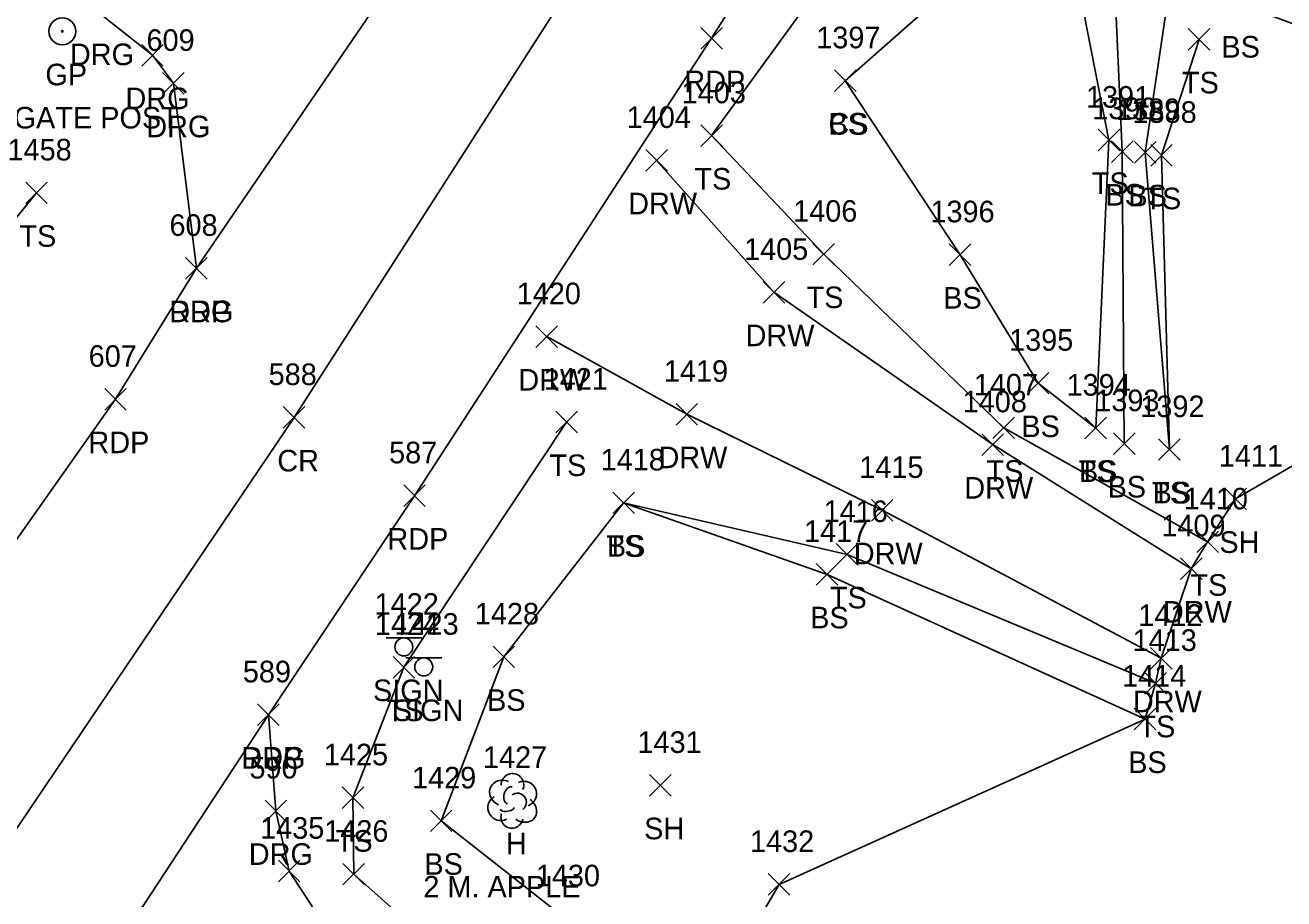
# Model space of a CAD drawing. Extents: x 1639430 to 1640195, y 612006 to 612917.
# Drawn here: x 1639665.7 to 1639782.3, y 612311.8 to 612392.7 of the extents above; entities that cross this region are included whole.
import ezdxf

# ---------------------------------------------------------------- set-up
doc = ezdxf.new("R2010")
doc.units = 0
for name, color, linetype in [('L_A', 7, 'Continuous'), ('L_C', 7, 'Continuous'), ('L_I', 7, 'Continuous'), ('L_TIC', 7, 'Continuous'), ('LELB', 7, 'Continuous'), ('LSOGP', 7, 'Continuous'), ('LTD', 7, 'Continuous'), ('P_A', 7, 'Continuous'), ('P_I', 7, 'Continuous'), ('P_TIC', 7, 'Continuous'), ('PET', 7, 'Continuous'), ('PRC', 7, 'Continuous'), ('R_A', 7, 'Continuous'), ('R_C', 7, 'Continuous'), ('R_I', 7, 'Continuous'), ('R_TIC', 7, 'Continuous'), ('RDG', 7, 'Continuous'), ('RDW', 7, 'Continuous'), ('RGP', 7, 'Continuous'), ('S_A', 7, 'Continuous'), ('S_I', 7, 'Continuous'), ('SSGN', 7, 'Continuous')]:
    doc.layers.add(name, color=color, linetype=linetype)

msp = doc.modelspace()

# ---------------------------------------------------------------- linework, layer by layer
at = {"layer": 'L_TIC'}
for points in [[(1639773.46, 612390.41), (1639775.46, 612392.41)], [(1639775.46, 612390.41), (1639773.46, 612392.41)], [(1639740.67, 612386.59), (1639742.67, 612388.59)], [(1639742.67, 612386.59), (1639740.67, 612388.59)], [(1639740.67, 612386.59), (1639742.67, 612388.59)], [(1639742.67, 612386.59), (1639740.67, 612388.59)], [(1639728.28, 612381.5), (1639730.28, 612383.5)], [(1639730.28, 612381.5), (1639728.28, 612383.5)], [(1639765.11, 612381.09), (1639767.11, 612383.09)], [(1639767.11, 612381.09), (1639765.11, 612383.09)], [(1639766.34, 612380.02), (1639768.34, 612382.02)], [(1639768.34, 612380.02), (1639766.34, 612382.02)], [(1639768.47, 612379.94), (1639770.47, 612381.94)], [(1639770.47, 612379.94), (1639768.47, 612381.94)], [(1639769.98, 612379.68), (1639771.98, 612381.68)], [(1639771.98, 612379.68), (1639769.98, 612381.68)], [(1639665.72, 612376.2), (1639667.72, 612378.2)], [(1639667.72, 612376.2), (1639665.72, 612378.2)], [(1639738.67, 612370.52), (1639740.67, 612372.52)], [(1639740.67, 612370.52), (1639738.67, 612372.52)], [(1639751.31, 612370.47), (1639753.31, 612372.47)], [(1639753.31, 612370.47), (1639751.31, 612372.47)], [(1639758.54, 612358.57), (1639760.54, 612360.57)], [(1639760.54, 612358.57), (1639758.54, 612360.57)], [(1639714.84, 612354.96), (1639716.84, 612356.96)], [(1639716.84, 612354.96), (1639714.84, 612356.96)], [(1639755.35, 612354.43), (1639757.35, 612356.43)], [(1639757.35, 612354.43), (1639755.35, 612356.43)], [(1639763.88, 612354.41), (1639765.88, 612356.41)], [(1639765.88, 612354.41), (1639763.88, 612356.41)], [(1639763.88, 612354.41), (1639765.88, 612356.41)], [(1639765.88, 612354.41), (1639763.88, 612356.41)], [(1639766.53, 612352.97), (1639768.53, 612354.97)], [(1639768.53, 612352.97), (1639766.53, 612354.97)], [(1639770.71, 612352.42), (1639772.71, 612354.42)], [(1639772.71, 612352.42), (1639770.71, 612354.42)], [(1639770.71, 612352.42), (1639772.71, 612354.42)], [(1639772.71, 612352.42), (1639770.71, 612354.42)], [(1639776.85, 612347.84), (1639778.85, 612349.84)], [(1639778.85, 612347.84), (1639776.85, 612349.84)], [(1639720.13, 612347.48), (1639722.13, 612349.48)], [(1639722.13, 612347.48), (1639720.13, 612349.48)], [(1639720.13, 612347.48), (1639722.13, 612349.48)], [(1639722.13, 612347.48), (1639720.13, 612349.48)], [(1639774.25, 612343.87), (1639776.25, 612345.87)], [(1639776.25, 612343.87), (1639774.25, 612345.87)], [(1639740.84, 612342.7), (1639742.84, 612344.7)], [(1639742.84, 612342.7), (1639740.84, 612344.7)], [(1639738.98, 612340.85), (1639740.98, 612342.85)], [(1639740.98, 612340.85), (1639738.98, 612342.85)], [(1639709.03, 612333.21), (1639711.03, 612335.21)], [(1639711.03, 612333.21), (1639709.03, 612335.21)], [(1639699.76, 612332.25), (1639701.76, 612334.25)], [(1639701.76, 612332.25), (1639699.76, 612334.25)], [(1639769.43, 612330.76), (1639771.43, 612332.76)], [(1639771.43, 612330.76), (1639769.43, 612332.76)], [(1639768.45, 612327.45), (1639770.45, 612329.45)], [(1639770.45, 612327.45), (1639768.45, 612329.45)], [(1639723.54, 612321.31), (1639725.54, 612323.31)], [(1639725.54, 612321.31), (1639723.54, 612323.31)], [(1639695.04, 612320.16), (1639697.04, 612322.16)], [(1639697.04, 612320.16), (1639695.04, 612322.16)], [(1639703.22, 612318.02), (1639705.22, 612320.02)], [(1639705.22, 612318.02), (1639703.22, 612320.02)], [(1639695.12, 612313.08), (1639697.12, 612315.08)], [(1639697.12, 612313.08), (1639695.12, 612315.08)], [(1639734.53, 612312.13), (1639736.53, 612314.13)], [(1639736.53, 612312.13), (1639734.53, 612314.13)]]:
    msp.add_lwpolyline(points, dxfattribs=at)
at = {"layer": 'LELB'}
for points in [[(1639767.47, 612437.46), (1639746.04, 612405.57), (1639729.28, 612382.5), (1639739.67, 612371.52), (1639756.35, 612355.43), (1639775.25, 612344.87)], [(1639741.67, 612387.59), (1639756.47, 612400.63), (1639762.87, 612412.76), (1639773.28, 612434.35)], [(1639832.09, 612385.7), (1639802.24, 612393.62), (1639781.12, 612401.39), (1639773.28, 612407.77), (1639764.29, 612408.76), (1639762.78, 612398.94), (1639766.11, 612382.09), (1639764.88, 612355.41)], [(1639826.23, 612376.84), (1639801.72, 612386.01), (1639778.09, 612394.73), (1639771.95, 612397.87), (1639769.65, 612405.44), (1639769.55, 612405.43), (1639768.09, 612406.04), (1639766.54, 612399.08), (1639767.34, 612381.02), (1639767.53, 612353.97)], [(1639771.95, 612397.87), (1639769.47, 612380.94), (1639771.71, 612353.42)], [(1639774.46, 612391.41), (1639770.98, 612380.68), (1639771.71, 612353.42)], [(1639764.88, 612355.41), (1639759.54, 612359.57), (1639752.31, 612371.47), (1639741.67, 612387.59)], [(1639600.03, 612336.44), (1639619.42, 612329.06), (1639644.87, 612350.34), (1639666.72, 612377.2)], [(1639715.84, 612355.96), (1639700.76, 612333.25), (1639696.04, 612321.16), (1639696.12, 612314.08), (1639722.58, 612290.54)], [(1639769.45, 612328.45), (1639739.98, 612341.85), (1639721.13, 612348.48), (1639710.03, 612334.21), (1639704.22, 612319.02), (1639715.77, 612309.95), (1639728.6, 612301.29)], [(1639770.43, 612331.76), (1639741.84, 612343.7), (1639721.13, 612348.48)]]:
    msp.add_lwpolyline(points, dxfattribs=at)
at = {"layer": 'LSOGP'}
msp.add_lwpolyline([(1639728.6, 612301.29), (1639735.53, 612313.13), (1639769.45, 612328.45), (1639770.43, 612331.76), (1639770.95, 612334.08), (1639773.74, 612342.38), (1639775.25, 612344.87), (1639777.85, 612348.84), (1639826.23, 612376.84), (1639832.09, 612385.7), (1639840.76, 612391.84), (1639840.72, 612407.15), (1639868.59, 612420.18)], dxfattribs=at)
at = {"layer": 'LTD'}
msp.add_line((1639710.79, 612320.92), (1639710.79, 612320.92), dxfattribs=at)
msp.add_line((1639710.79, 612320.92), (1639710.79, 612320.92), dxfattribs=at)
msp.add_arc((1639710.83, 612322.35), 1.05, 335.5272, 180.9563, dxfattribs=at)
for centre, major_axis, ratio, start_param, end_param in [((1639710, 612321.59), (1.21, -0.51), 0.895232, 1.570796, 4.712389), ((1639711.83, 612321.5), (-1.14, -0.48), 0.949671, 1.570796, 4.712389), ((1639710.58, 612321.38), (-0.208, -0.792), 0.645439, 3.141593, 6.283185), ((1639711.29, 612320.75), (-0.5, 0.667), 0.989748, 3.141593, 6.283185), ((1639709.7, 612320.21), (0.58, -1.04), 0.959034, 3.141593, 6.283185), ((1639711.79, 612320.09), (-1.09, 0.79), 0.841452, 1.570796, 4.712389), ((1639710.79, 612319.42), (0.26, 1.06), 0.942809, 1.570796, 4.712389), ((1639710.33, 612320.17), (-0.625, -0.083), 0.423636, 0, 3.141593)]:
    msp.add_ellipse(centre, major_axis=major_axis, ratio=ratio, start_param=start_param, end_param=end_param, dxfattribs=at)
at = {"layer": 'P_TIC'}
for points in [[(1639728.28, 612390.52), (1639730.28, 612392.52)], [(1639730.28, 612390.52), (1639728.28, 612392.52)], [(1639680.53, 612369.21), (1639682.53, 612371.21)], [(1639682.53, 612369.21), (1639680.53, 612371.21)], [(1639673.04, 612357.08), (1639675.04, 612359.08)], [(1639675.04, 612357.08), (1639673.04, 612359.08)], [(1639689.59, 612355.39), (1639691.59, 612357.39)], [(1639691.59, 612355.39), (1639689.59, 612357.39)], [(1639700.75, 612348.14), (1639702.75, 612350.14)], [(1639702.75, 612348.14), (1639700.75, 612350.14)], [(1639687.21, 612327.85), (1639689.21, 612329.85)], [(1639689.21, 612327.85), (1639687.21, 612329.85)]]:
    msp.add_lwpolyline(points, dxfattribs=at)
at = {"layer": 'PET'}
for points in [[(1639571.61, 612204.8), (1639581.27, 612221.94), (1639610.12, 612263.74), (1639636.18, 612301.91), (1639636.72, 612305.17), (1639674.04, 612358.08), (1639681.53, 612370.21), (1639706.2, 612406.33), (1639726.2, 612437.98), (1639749.36, 612475.33)], [(1639757.28, 612435.5), (1639729.28, 612391.52), (1639701.75, 612349.14), (1639688.21, 612328.85), (1639670.81, 612302.33), (1639642.67, 612258.91), (1639622.85, 612231.41), (1639592.08, 612186.98)]]:
    msp.add_lwpolyline(points, dxfattribs=at)
at = {"layer": 'PRC'}
msp.add_lwpolyline([(1639744.51, 612441.45), (1639719.17, 612400.96), (1639690.59, 612356.39), (1639658.59, 612309.05), (1639630.32, 612267.52), (1639611.01, 612239.3), (1639581.06, 612195.34)], dxfattribs=at)
at = {"layer": 'R_TIC'}
for points in [[(1639676.47, 612388.95), (1639678.47, 612390.95)], [(1639678.47, 612388.95), (1639676.47, 612390.95)], [(1639678.4, 612386.35), (1639680.4, 612388.35)], [(1639680.4, 612386.35), (1639678.4, 612388.35)], [(1639723.18, 612379.21), (1639725.18, 612381.21)], [(1639725.18, 612379.21), (1639723.18, 612381.21)], [(1639680.53, 612369.21), (1639682.53, 612371.21)], [(1639682.53, 612369.21), (1639680.53, 612371.21)], [(1639734.06, 612366.99), (1639736.06, 612368.99)], [(1639736.06, 612366.99), (1639734.06, 612368.99)], [(1639713, 612362.88), (1639715, 612364.88)], [(1639715, 612362.88), (1639713, 612364.88)], [(1639725.99, 612355.69), (1639727.99, 612357.69)], [(1639727.99, 612355.69), (1639725.99, 612357.69)], [(1639754.33, 612352.87), (1639756.33, 612354.87)], [(1639756.33, 612352.87), (1639754.33, 612354.87)], [(1639744.09, 612346.79), (1639746.09, 612348.79)], [(1639746.09, 612346.79), (1639744.09, 612348.79)], [(1639772.74, 612341.38), (1639774.74, 612343.38)], [(1639774.74, 612341.38), (1639772.74, 612343.38)], [(1639769.95, 612333.08), (1639771.95, 612335.08)], [(1639771.95, 612333.08), (1639769.95, 612335.08)], [(1639687.21, 612327.85), (1639689.21, 612329.85)], [(1639689.21, 612327.85), (1639687.21, 612329.85)], [(1639687.9, 612318.94), (1639689.9, 612320.94)], [(1639689.9, 612318.94), (1639687.9, 612320.94)], [(1639689.13, 612313.36), (1639691.13, 612315.36)], [(1639691.13, 612313.36), (1639689.13, 612315.36)]]:
    msp.add_lwpolyline(points, dxfattribs=at)
at = {"layer": 'RDG'}
for points in [[(1639635.96, 612403.52), (1639655.88, 612404.43), (1639672.32, 612394.03), (1639677.47, 612389.95)], [(1639679.4, 612387.35), (1639677.47, 612389.95)], [(1639681.53, 612370.21), (1639679.4, 612387.35)], [(1639688.21, 612328.85), (1639688.9, 612319.94)], [(1639688.9, 612319.94), (1639690.13, 612314.36)], [(1639690.13, 612314.36), (1639695.68, 612305.83), (1639719.34, 612285.44)]]:
    msp.add_lwpolyline(points, dxfattribs=at)
at = {"layer": 'RDW'}
for points in [[(1639724.18, 612380.21), (1639735.06, 612367.99), (1639755.33, 612353.87), (1639773.74, 612342.38)], [(1639770.95, 612334.08), (1639745.09, 612347.79), (1639726.99, 612356.69), (1639714, 612363.88)]]:
    msp.add_lwpolyline(points, dxfattribs=at)
at = {"layer": 'RGP'}
msp.add_line((1639669.11, 612392.16), (1639669.11, 612392.16), dxfattribs=at)
for radius in [1.25, 0.0833]:
    msp.add_circle((1639669.11, 612392.16), radius, dxfattribs=at)
at = {"layer": 'SSGN'}
for p, q in [((1639699.11, 612335.96), (1639702.44, 612335.96)), ((1639700.76, 612335.13), (1639700.76, 612335.13)), ((1639700.95, 612334.11), (1639704.29, 612334.11)), ((1639702.6, 612333.28), (1639702.6, 612333.28))]:
    msp.add_line(p, q, dxfattribs=at)
for centre in [(1639700.76, 612335.13), (1639702.6, 612333.28)]:
    msp.add_circle(centre, 0.833, dxfattribs=at)

# ---------------------------------------------------------------- texts
at = {"layer": 'L_A'}
for s, p in [('BS', (1639776.53, 612389.73)), ('TS', (1639772.87, 612386.41)), ('CS', (1639740.11, 612382.59)), ('BS', (1639740.11, 612382.59)), ('TS', (1639727.69, 612377.5)), ('TS', (1639764.52, 612377.09)), ('BS', (1639765.78, 612376.02)), ('BS', (1639767.91, 612375.94)), ('TS', (1639769.39, 612375.68)), ('TS', (1639665.13, 612372.2)), ('TS', (1639738.08, 612366.52)), ('BS', (1639750.75, 612366.47)), ('BS', (1639757.99, 612354.57)), ('TS', (1639714.25, 612350.96)), ('TS', (1639754.76, 612350.43)), ('TS', (1639763.29, 612350.41)), ('BS', (1639763.32, 612350.41)), ('BS', (1639765.98, 612348.97)), ('TS', (1639770.11, 612348.42)), ('BS', (1639770.15, 612348.42)), ('TS', (1639719.54, 612343.48)), ('BS', (1639719.57, 612343.48)), ('SH', (1639776.34, 612343.84)), ('TS', (1639773.66, 612339.87)), ('TS', (1639740.25, 612338.7)), ('BS', (1639738.42, 612336.85)), ('BS', (1639708.47, 612329.21)), ('TS', (1639699.17, 612328.25)), ('TS', (1639768.84, 612326.76)), ('BS', (1639767.89, 612323.45)), ('SH', (1639723.03, 612317.31)), ('TS', (1639694.45, 612316.16)), ('H', (1639710.22, 612315.92)), ('BS', (1639702.66, 612314.02))]:
    msp.add_text(s, height=2, dxfattribs=at).set_placement(p)
at = {"layer": 'L_C'}
msp.add_text('2 M. APPLE', height=2, dxfattribs=at).set_placement((1639702.57, 612311.92))
at = {"layer": 'L_I'}
for s, p in [('1397', (1639738.98, 612390.59)), ('1397', (1639738.98, 612390.59)), ('1403', (1639726.51, 612385.5)), ('1391', (1639763.98, 612385.09)), ('1390', (1639764.56, 612384.02)), ('1389', (1639766.77, 612383.94)), ('1388', (1639768.29, 612383.68)), ('1458', (1639664.03, 612380.2)), ('1406', (1639736.84, 612374.52)), ('1396', (1639749.56, 612374.47)), ('1395', (1639756.85, 612362.57)), ('1421', (1639713.72, 612358.96)), ('1407', (1639753.58, 612358.43)), ('1394', (1639762.18, 612358.41)), ('1394', (1639762.18, 612358.41)), ('1393', (1639764.84, 612356.97)), ('1392', (1639769.01, 612356.42)), ('1392', (1639769.01, 612356.42)), ('1418', (1639719, 612351.48)), ('1418', (1639719, 612351.48)), ('1411', (1639776.29, 612351.84)), ('1410', (1639773.04, 612347.87)), ('1416', (1639739.66, 612346.7)), ('1417', (1639737.85, 612344.85)), ('1428', (1639707.34, 612337.21)), ('1424', (1639698.07, 612336.25)), ('1413', (1639768.3, 612334.76)), ('1414', (1639767.32, 612331.45)), ('1431', (1639722.41, 612325.31)), ('1425', (1639693.35, 612324.16)), ('1427', (1639708.09, 612323.92)), ('1429', (1639701.52, 612322.02)), ('1426', (1639693.38, 612317.08)), ('1432', (1639732.84, 612316.13)), ('1430', (1639712.99, 612312.95))]:
    msp.add_text(s, height=2, dxfattribs=at).set_placement(p)
at = {"layer": 'P_A'}
for s, p in [('RDP', (1639726.76, 612386.52)), ('RDP', (1639679.02, 612365.21)), ('RDP', (1639671.53, 612353.08)), ('CR', (1639689.03, 612351.39)), ('RDP', (1639699.24, 612344.14)), ('RDP', (1639685.7, 612323.85))]:
    msp.add_text(s, height=2, dxfattribs=at).set_placement(p)
at = {"layer": 'P_I'}
for s, p in [('608', (1639679.04, 612373.21)), ('607', (1639671.55, 612361.08)), ('588', (1639688.23, 612359.39)), ('587', (1639699.39, 612352.14)), ('589', (1639685.84, 612331.85))]:
    msp.add_text(s, height=2, dxfattribs=at).set_placement(p)
at = {"layer": 'R_A'}
for s, p in [('DRG', (1639669.81, 612389.03)), ('GP', (1639667.54, 612387.16)), ('DRG', (1639674.96, 612384.95)), ('DRG', (1639676.89, 612382.35)), ('DRW', (1639721.55, 612375.21)), ('DRG', (1639679.02, 612365.21)), ('DRW', (1639732.43, 612362.99)), ('DRW', (1639711.37, 612358.88)), ('DRW', (1639724.36, 612351.69)), ('DRW', (1639752.7, 612348.87)), ('DRW', (1639742.46, 612342.79)), ('DRW', (1639771.11, 612337.38)), ('DRW', (1639768.32, 612329.08)), ('DRG', (1639685.7, 612323.85)), ('DRG', (1639686.39, 612314.94))]:
    msp.add_text(s, height=2, dxfattribs=at).set_placement(p)
at = {"layer": 'R_C'}
msp.add_text('STEEL GATE POST', height=2, dxfattribs=at).set_placement((1639655.38, 612383.16))
at = {"layer": 'R_I'}
for s, p in [('609', (1639676.91, 612390.35)), ('1404', (1639721.41, 612383.21)), ('608', (1639679.04, 612373.21)), ('1405', (1639732.29, 612370.99)), ('1420', (1639711.22, 612366.88)), ('1419', (1639724.86, 612359.69)), ('1408', (1639752.55, 612356.87)), ('1415', (1639742.97, 612350.79)), ('1409', (1639770.96, 612345.38)), ('1412', (1639768.82, 612337.08)), ('589', (1639685.84, 612331.85)), ('590', (1639686.45, 612322.94)), ('1435', (1639687.44, 612317.36))]:
    msp.add_text(s, height=2, dxfattribs=at).set_placement(p)
at = {"layer": 'S_A'}
for p in [(1639697.9, 612330.11), (1639699.74, 612328.26)]:
    msp.add_text('SIGN', height=2, dxfattribs=at).set_placement(p)
at = {"layer": 'S_I'}
for s, p in [('1422', (1639698.05, 612338.11)), ('1423', (1639699.89, 612336.26))]:
    msp.add_text(s, height=2, dxfattribs=at).set_placement(p)

doc.saveas('drawing.dxf')
